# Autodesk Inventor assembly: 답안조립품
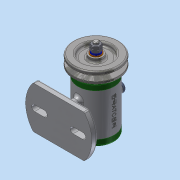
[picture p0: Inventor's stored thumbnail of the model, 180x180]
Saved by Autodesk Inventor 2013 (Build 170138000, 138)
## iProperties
Created: 2017-12
Part Number: 답안조립품
Document SubType Name: Assembly
Designer: Administrator
Author: Administrator
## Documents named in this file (14)
- C:\Users\Administrator\Desktop\471208V1028\답안조립품.iam
- C:\Users\Administrator\Desktop\471208V1028\V벨트풀리.ipt
- C:\Users\Administrator\Desktop\471208V1028\고무캡.ipt
- C:\Users\Administrator\Desktop\471208V1028\너트 M 8.ipt
- C:\Users\Administrator\Desktop\471208V1028\뒤커버.ipt
- C:\Users\Administrator\Desktop\471208V1028\베어링 15 x 32 x 9.ipt
- C:\Users\Administrator\Desktop\471208V1028\본체.ipt
- C:\Users\Administrator\Desktop\471208V1028\볼트 M4 x 12.ipt
- C:\Users\Administrator\Desktop\471208V1028\스프링와셔 8.ipt
- C:\Users\Administrator\Desktop\471208V1028\앞커버.ipt
- C:\Users\Administrator\Desktop\471208V1028\오일 실 15 25 7.ipt
- C:\Users\Administrator\Desktop\471208V1028\와셔 8x17.ipt
- C:\Users\Administrator\Desktop\471208V1028\축.ipt
- C:\Users\Administrator\Desktop\471208V1028\키 3 x 3 x 12.ipt
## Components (2 placed, 2 different names)
1. V벨트풀리:1
2. 고무캡:1
